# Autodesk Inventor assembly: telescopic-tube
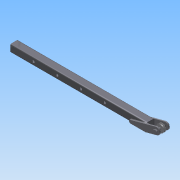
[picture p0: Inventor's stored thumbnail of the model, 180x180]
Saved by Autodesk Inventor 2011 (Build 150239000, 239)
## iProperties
Created: 2020-12
Part Number: telescopic-tube
Document SubType Name: Weldment
Designer: PC
Weld Material: Welded Steel Mild
Author: PC
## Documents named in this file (4)
- C:\Users\PC\Documents\Inventor\workshop-crane-powered-by-drill\telescopic-tube.iam
- C:\Users\PC\Documents\Inventor\workshop-crane-powered-by-drill\3_tubo-telescopico.iam
- C:\Users\PC\Documents\Inventor\workshop-crane-powered-by-drill\telescopic-tube\Design Accelerator\Bolted Connection1.iam
- C:\Users\PC\Documents\Inventor\workshop-crane-powered-by-drill\pulley.ipt
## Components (3 placed, 3 different names)
1. 3_tubo-telescopico:1 [sub-assembly] — Mate:1, Mate:2, Insert:1
2. Bolted Connection:1 [sub-assembly] — Mate:1, Mate:2
3. pulley:1 — Insert:1
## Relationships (3: Mate 2, Insert 1)
- Mate:1: 3_tubo-telescopico:1 ↔ Bolted Connection:1
- Mate:2: 3_tubo-telescopico:1 ↔ Bolted Connection:1
- Insert:1: 3_tubo-telescopico:1 ↔ pulley:1
